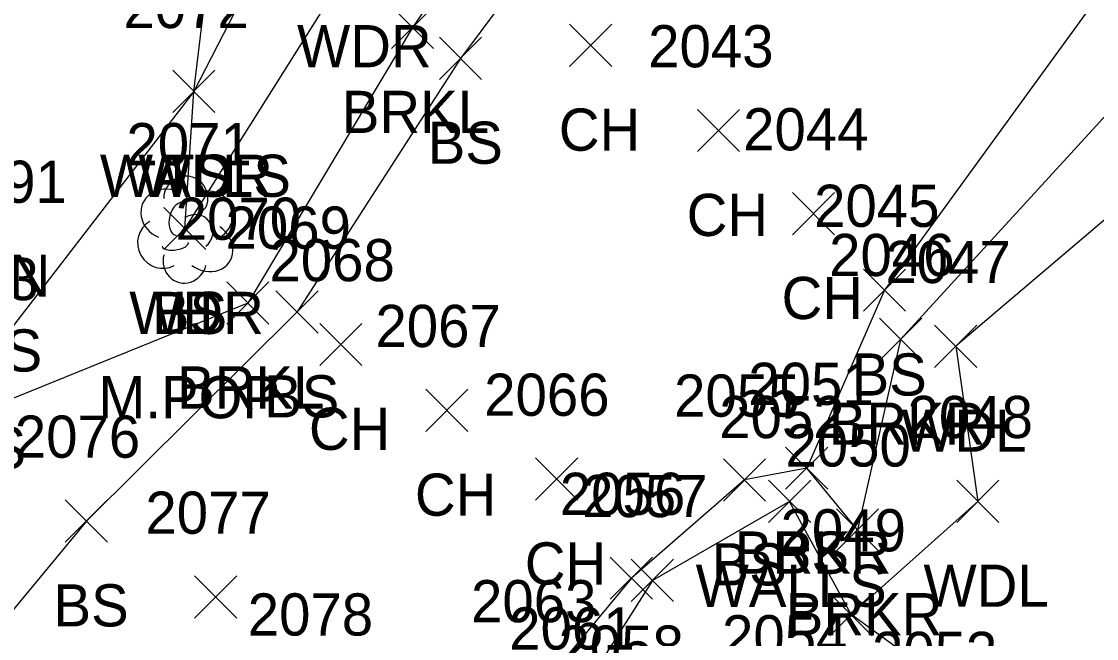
# Model space of a CAD drawing. Extents: x 1499292 to 1501024, y 534584 to 538043.
# Drawn here: x 1499836.8 to 1499887.8, y 537704.6 to 537733.8 of the extents above; entities that cross this region are included whole.
import ezdxf

# ---------------------------------------------------------------- set-up
doc = ezdxf.new("R2010")
doc.units = 0
for name, color, linetype in [('L_A', 7, 'Continuous'), ('L_C', 7, 'Continuous'), ('L_I', 7, 'Continuous'), ('L_TIC', 7, 'Continuous'), ('LAWA', 7, 'Continuous'), ('LAWE', 7, 'Continuous'), ('LELB', 7, 'Continuous'), ('LTD', 7, 'Continuous'), ('LWS', 7, 'Continuous')]:
    doc.layers.add(name, color=color, linetype=linetype)

msp = doc.modelspace()

# ---------------------------------------------------------------- linework, layer by layer
at = {"layer": 'L_TIC'}
for points in [[(1499854.373, 537732.552), (1499856.373, 537734.552)], [(1499856.373, 537732.552), (1499854.373, 537734.552)], [(1499862.828, 537731.711), (1499864.828, 537733.711)], [(1499864.828, 537731.711), (1499862.828, 537733.711)], [(1499856.652, 537731.091), (1499858.652, 537733.091)], [(1499858.652, 537731.091), (1499856.652, 537733.091)], [(1499843.995, 537729.524), (1499845.995, 537731.524)], [(1499845.995, 537729.524), (1499843.995, 537731.524)], [(1499843.995, 537729.524), (1499845.995, 537731.524)], [(1499845.995, 537729.524), (1499843.995, 537731.524)], [(1499843.995, 537729.524), (1499845.995, 537731.524)], [(1499845.995, 537729.524), (1499843.995, 537731.524)], [(1499868.892, 537727.667), (1499870.892, 537729.667)], [(1499870.892, 537727.667), (1499868.892, 537729.667)], [(1499873.396, 537723.727), (1499875.396, 537725.727)], [(1499875.396, 537723.727), (1499873.396, 537725.727)], [(1499843.571, 537723.022), (1499845.571, 537725.022)], [(1499845.571, 537723.022), (1499843.571, 537725.022)], [(1499843.571, 537723.022), (1499845.571, 537725.022)], [(1499845.571, 537723.022), (1499843.571, 537725.022)], [(1499876.766, 537720.1), (1499878.766, 537722.1)], [(1499878.766, 537720.1), (1499876.766, 537722.1)], [(1499846.561, 537719.487), (1499848.561, 537721.487)], [(1499848.561, 537719.487), (1499846.561, 537721.487)], [(1499848.894, 537719.064), (1499850.894, 537721.064)], [(1499850.894, 537719.064), (1499848.894, 537721.064)], [(1499877.532, 537717.766), (1499879.532, 537719.766)], [(1499879.532, 537717.766), (1499877.532, 537719.766)], [(1499850.97, 537717.523), (1499852.97, 537719.523)], [(1499852.97, 537717.523), (1499850.97, 537719.523)], [(1499880.146, 537717.435), (1499882.146, 537719.435)], [(1499882.146, 537717.435), (1499880.146, 537719.435)], [(1499855.998, 537714.401), (1499857.998, 537716.401)], [(1499857.998, 537714.401), (1499855.998, 537716.401)], [(1499873.077, 537711.657), (1499875.077, 537713.657)], [(1499875.077, 537711.657), (1499873.077, 537713.657)], [(1499873.077, 537711.657), (1499875.077, 537713.657)], [(1499875.077, 537711.657), (1499873.077, 537713.657)], [(1499861.214, 537711.14), (1499863.214, 537713.14)], [(1499863.214, 537711.14), (1499861.214, 537713.14)], [(1499870.122, 537711.1), (1499872.122, 537713.1)], [(1499872.122, 537711.1), (1499870.122, 537713.1)], [(1499872.264, 537710.082), (1499874.264, 537712.082)], [(1499874.264, 537710.082), (1499872.264, 537712.082)], [(1499881.199, 537710.084), (1499883.199, 537712.084)], [(1499883.199, 537710.084), (1499881.199, 537712.084)], [(1499838.898, 537709.152), (1499840.898, 537711.152)], [(1499840.898, 537709.152), (1499838.898, 537711.152)], [(1499875.489, 537708.735), (1499877.489, 537710.735)], [(1499877.489, 537708.735), (1499875.489, 537710.735)], [(1499864.758, 537706.441), (1499866.758, 537708.441)], [(1499866.758, 537706.441), (1499864.758, 537708.441)], [(1499865.755, 537706.335), (1499867.755, 537708.335)], [(1499867.755, 537706.335), (1499865.755, 537708.335)], [(1499845.036, 537705.547), (1499847.036, 537707.547)], [(1499847.036, 537705.547), (1499845.036, 537707.547)], [(1499875.181, 537704.711), (1499877.181, 537706.711)], [(1499877.181, 537704.711), (1499875.181, 537706.711)], [(1499875.181, 537704.711), (1499877.181, 537706.711)], [(1499877.181, 537704.711), (1499875.181, 537706.711)], [(1499875.181, 537704.711), (1499877.181, 537706.711)], [(1499877.181, 537704.711), (1499875.181, 537706.711)]]:
    msp.add_lwpolyline(points, dxfattribs=at)
at = {"layer": 'LAWA'}
for points in [[(1499965.845, 537814.607), (1499956.806, 537795.15), (1499949.698, 537786.608), (1499937.814, 537776.416), (1499929.69, 537766.375), (1499922.293, 537760.072), (1499904.962, 537742.29), (1499895.527, 537730.646), (1499881.146, 537718.435), (1499882.199, 537711.084), (1499876.181, 537705.711)], [(1499972.434, 537809.149), (1499962.707, 537789.685), (1499956.245, 537767.268), (1499944.762, 537752.791), (1499936.939, 537741.705), (1499930.814, 537724.983), (1499924.568, 537711.676), (1499920.036, 537699.678), (1499913.288, 537691.152), (1499908.677, 537691.352), (1499901.029, 537688.053), (1499897.226, 537689.74), (1499889.261, 537696.2), (1499876.181, 537705.711)], [(1499880.443, 537784.782), (1499883.283, 537782.612), (1499885.891, 537781.165), (1499875.842, 537768.227), (1499865.392, 537753.067), (1499852.532, 537736.668), (1499844.571, 537724.022), (1499844.995, 537730.524)], [(1499844.995, 537730.524), (1499846.549, 537743.391)]]:
    msp.add_lwpolyline(points, dxfattribs=at)
at = {"layer": 'LAWE'}
for points in [[(1499929.735, 537843.158), (1499921.146, 537828.37), (1499911.208, 537810.95), (1499902.71, 537799.071), (1499891.697, 537780.61), (1499878.475, 537765.999), (1499867.221, 537750.797), (1499855.373, 537733.552), (1499847.561, 537720.487), (1499833.234, 537714.677)], [(1499961.233, 537817.956), (1499952.785, 537802.28), (1499941.102, 537783.95), (1499931.596, 537774.682), (1499919.4, 537762.854), (1499904.496, 537744.851), (1499892.595, 537734.118), (1499878.532, 537718.766), (1499876.489, 537709.735), (1499874.077, 537712.657)]]:
    msp.add_lwpolyline(points, dxfattribs=at)
at = {"layer": 'LELB'}
for points in [[(1499931.33, 537841.299), (1499922.805, 537827.368), (1499912.716, 537807.848), (1499905.961, 537796.116), (1499895.821, 537778.011), (1499880.547, 537762.563), (1499870.857, 537749.776), (1499857.652, 537732.091), (1499849.894, 537720.064), (1499839.898, 537710.152), (1499830.869, 537699.252), (1499819.753, 537691.274), (1499813.247, 537682.443), (1499807.235, 537678.729), (1499801.402, 537680.954), (1499789.916, 537664.219), (1499779.135, 537655.089), (1499771.857, 537652.255), (1499758.583, 537645.464), (1499745.452, 537639.294), (1499734.398, 537633.246), (1499715.956, 537632.699), (1499700.464, 537632.224)], [(1499958.724, 537820.121), (1499949.099, 537803.701), (1499937.207, 537786.88), (1499926.5, 537779.141), (1499915.434, 537766.609), (1499901.39, 537746.714), (1499889.513, 537737.266), (1499877.766, 537721.1), (1499874.077, 537712.657), (1499871.122, 537712.1), (1499865.758, 537707.441), (1499861.535, 537702.351), (1499859.643, 537699.06)], [(1499844.995, 537730.524), (1499835.027, 537717.621)]]:
    msp.add_lwpolyline(points, dxfattribs=at)
at = {"layer": 'LTD'}
msp.add_line((1499844.571, 537724.022), (1499844.571, 537724.022), dxfattribs=at)
msp.add_line((1499844.571, 537724.022), (1499844.571, 537724.022), dxfattribs=at)
msp.add_arc((1499844.617, 537725.456), 1.047, 335.5272, 180.9563, dxfattribs=at)
for centre, major_axis, ratio, start_param, end_param in [((1499843.779, 537724.689), (1.21, -0.512), 0.895232, 1.570796, 4.712389), ((1499845.612, 537724.606), (-1.141, -0.483), 0.949671, 1.570796, 4.712389), ((1499844.362, 537724.48), (-0.208, -0.792), 0.645439, 3.141593, 6.283185), ((1499845.071, 537723.855), (-0.5, 0.667), 0.989748, 3.141593, 6.283185), ((1499843.487, 537723.313), (0.584, -1.042), 0.959034, 3.141593, 6.283185), ((1499845.571, 537723.189), (-1.09, 0.792), 0.841452, 1.570796, 4.712389), ((1499844.112, 537723.272), (-0.625, -0.083), 0.423636, 0, 3.141593), ((1499844.571, 537722.522), (0.265, 1.061), 0.942809, 1.570796, 4.712389)]:
    msp.add_ellipse(centre, major_axis=major_axis, ratio=ratio, start_param=start_param, end_param=end_param, dxfattribs=at)
at = {"layer": 'LWS'}
for points in [[(1499897.801, 537803.789), (1499891.884, 537793.964), (1499883.283, 537782.612), (1499874.394, 537769.047), (1499862.601, 537755.249), (1499849.481, 537739.229), (1499844.995, 537730.524)], [(1499876.181, 537705.711), (1499873.264, 537711.082), (1499866.755, 537707.335), (1499862.781, 537701.056), (1499861.431, 537698.979)]]:
    msp.add_lwpolyline(points, dxfattribs=at)

# ---------------------------------------------------------------- texts
at = {"layer": 'L_A'}
for s, p in [('WDR', (1499849.894, 537731.668)), ('BRKL', (1499852.019, 537728.552)), ('CH', (1499862.316, 537727.711)), ('BS', (1499856.093, 537727.091)), ('WALLS', (1499840.538, 537725.524)), ('WDR', (1499842.357, 537725.524)), ('TS', (1499843.404, 537725.524)), ('CH', (1499868.38, 537723.667)), ('GARDEN', (1499826.741, 537720.788)), ('CH', (1499872.884, 537719.727)), ('WDR', (1499841.933, 537719.022)), ('BS', (1499843.011, 537719.022)), ('H', (1499844.004, 537719.022)), ('BS', (1499834.236, 537717.239)), ('BS', (1499834.236, 537717.239)), ('BS', (1499876.207, 537716.1)), ('BRKL', (1499844.206, 537715.487)), ('BS', (1499848.335, 537715.064)), ('BRKR', (1499875.123, 537713.766)), ('CH', (1499850.458, 537713.523)), ('WDL', (1499878.563, 537713.435)), ('BS', (1499833.468, 537712.621)), ('CH', (1499855.487, 537710.401)), ('BRKR', (1499870.667, 537707.657)), ('BS', (1499872.518, 537707.657)), ('CH', (1499860.702, 537707.14)), ('BS', (1499869.563, 537707.1)), ('WALLS', (1499868.807, 537706.082)), ('WDL', (1499879.617, 537706.084)), ('BS', (1499838.339, 537705.152)), ('BRKR', (1499873.08, 537704.735))]:
    msp.add_text(s, height=2, dxfattribs=at).set_placement(p)
at = {"layer": 'L_C'}
msp.add_text('M.POP', height=2, dxfattribs=at).set_placement((1499840.468, 537715.022))
at = {"layer": 'L_I'}
for s, p in [('2072', (1499841.656, 537733.524)), ('2072', (1499841.656, 537733.524)), ('2072', (1499841.656, 537733.524)), ('2043', (1499866.554, 537731.667)), ('2044', (1499871.058, 537727.727)), ('2071', (1499841.799, 537727.022)), ('2071', (1499841.799, 537727.022)), ('2071', (1499841.799, 537727.022)), ('3091', (1499833.023, 537725.239)), ('3091', (1499833.023, 537725.239)), ('2045', (1499874.427, 537724.1)), ('2070', (1499844.135, 537723.487)), ('2069', (1499846.5, 537723.064)), ('2046', (1499875.139, 537721.766)), ('2068', (1499848.584, 537721.523)), ('2047', (1499877.807, 537721.435)), ('2073', (1499831.689, 537720.621)), ('2073', (1499831.689, 537720.621)), ('2067', (1499853.613, 537718.401)), ('2051', (1499871.305, 537715.657)), ('2051', (1499871.305, 537715.657)), ('2066', (1499858.773, 537715.14)), ('2055', (1499867.784, 537715.1)), ('2052', (1499869.925, 537714.082)), ('2048', (1499878.861, 537714.084)), ('2076', (1499836.504, 537713.152)), ('2050', (1499873.064, 537712.735)), ('2056', (1499862.364, 537710.441)), ('2057', (1499863.417, 537710.335)), ('2077', (1499842.697, 537709.547)), ('2049', (1499872.834, 537708.711)), ('2049', (1499872.834, 537708.711)), ('2049', (1499872.834, 537708.711)), ('2063', (1499858.149, 537705.351)), ('2078', (1499847.555, 537704.72)), ('2061', (1499859.962, 537704.056)), ('2054', (1499870.058, 537703.686)), ('2058', (1499862.299, 537703.196)), ('2053', (1499877.172, 537702.897))]:
    msp.add_text(s, height=2, dxfattribs=at).set_placement(p)

doc.saveas('drawing.dxf')
